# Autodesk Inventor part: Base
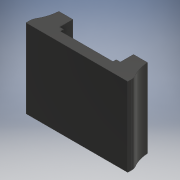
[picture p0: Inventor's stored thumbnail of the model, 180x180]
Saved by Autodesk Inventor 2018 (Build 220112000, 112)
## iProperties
Created: 2022-01
Part Number: Base
Material: Plástico, negro opaco
Document SubType Name: Modelado
Designer: Asus
Density: 0.952 g/cm^3
Appearance: Suave - Negro
Author: Asus
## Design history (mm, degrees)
sketch "Boceto1"
  geometry: L1 (135, 120)-(-135, 120); L2 (-135, 120)-(-135, -120); L3 (-135, -120)-(135, -120); L4 (135, -120)-(135, 120); L5 (135, 120)-(-135, -120); L6 (-135, 120)-(135, -120); 1 further point
  constraints: 12 end point, 2 midpoint, 2 parallel, 1 horizontal, 1 perpendicular
  dimensions: "d0" = 270 distance of L3.end L2.end; "d1" = 240 distance of L2.end L1.end
extrude "Extrusión1" new body sketch "Boceto1" distance "d2" = 80; taper "d3" = 0 deg
sketch "Boceto2"
  geometry: L1 (0, 120)-(80, 120) reference; L2 (80, 120)-(80, -120) reference; L3 (80, -120)-(0, -120) reference; L4 (0, -120)-(0, 120) reference; L5 (0, 120)-(80, 120) reference; L6 (80, 120)-(80, -120) reference; L7 (80, -120)-(0, -120) reference; L8 (0, -120)-(0, 120) reference; L9 (0, 120)-(80, 120) reference; L10 (80, 120)-(80, -120) reference; L11 (80, -120)-(0, -120) reference; L12 (0, -120)-(0, 120) reference; L13 (0, 120)-(80, 120) reference; L14 (80, 120)-(80, -120) reference; L15 (80, -120)-(0, -120) reference; L16 (0, -120)-(0, 120) reference; L17 (0, 120)-(80, 120) reference; L18 (80, 120)-(80, -120) reference; L19 (80, -120)-(0, -120) reference; L20 (0, -120)-(0, 120) reference; L21 (80, 120)-(30, 120); L22 (0, 120)-(80, 120) reference; L23 (0, -120)-(80, -120) reference; L24 (30, 120)-(80, -120); L25 (80, -120)-(80, 120); 1 further point
  constraints: 6 end point, 1 perpendicular, 1 point on line
  dimensions: "d4" = 50 distance of L1.end L21.end
extrude "Extrusión2" cut sketch "Boceto2" stored distance "d5" = 160; taper "d6" = 0 deg
sketch "Boceto3"
  geometry: L1 (-120, 0)-(-120, 80) reference; L2 (-120, 80)-(-120, 40); L3 (-120, 80)-(0, 80); L4 (120, 80)-(-120, 80) reference; L5 (0, 80)-(0, 20); L6 (0, 20)-(-20, 20); L7 (-20, 20)-(-20, 40); L8 (-20, 40)-(-120, 40); 1 further point
  constraints: 12 end point, 2 midpoint, 2 perpendicular, 1 horizontal
  dimensions: "d8" = 40 distance of L1.end L2.end; "d9" = 120 distance of L1.end L3.end (derived); "d10" = 60 distance of L3.end L5.end; "d11" = 20 distance of L5.end L6.end; "d12" = 20 distance of L6.end L7.end
extrude "Extrusión3" cut sketch "Boceto3" distance "d13" = 12.5; taper "d14" = 0 deg
sketch "Boceto4"
  geometry: L1 (0, 80)-(0, 20); L2 (0, 80)-(120, 80); L3 (120, 80)-(120, 40); L4 (0, 20)-(20, 20); L5 (20, 20)-(20, 40); L6 (20, 40)-(120, 40); 3 further points
  constraints: 12 end point, 1 horizontal, 1 perpendicular
  dimensions: "d16" = 120 distance of point (-120, 80) L1.start (derived); "d17" = 60 distance of L1.start L1.end; "d20" = 20 distance of L1.end L4.end; "d21" = 20 distance of L4.end L5.end
extrude "Extrusión4" cut sketch "Boceto4" distance "d22" = 12.5; taper "d23" = 0 deg
sketch "Boceto5"
  geometry: L1 (0, 0)-(-20, 0); L2 (-20, 0)-(-20, 20); L3 (270, 0)-(270, 80) reference; L4 (270, 80)-(270, 0); L5 (270, 0)-(290, 0); L6 (290, 0)-(290, 20); L7 (270, 0)-(0, 0) reference; L8 (0, 80)-(55, 80) reference; L9 (0, 0)-(0, 80); A1 r 122.729 centre (-122.5, 87.5) between (-20, 20) and (0, 80); A2 r 122.729 centre (392.5, 87.5) between (270, 80) and (290, 20); 1 further point
  constraints: 12 end point, 4 perpendicular, 4 point on circle, 2 centre point, 1 collinear, 1 horizontal
  dimensions: "d24" = 20 distance of L1.start L1.end; "d25" = 20 distance of L1.end L2.end; "d26" = 20 distance of L3.start L5.end; "d27" = 20 distance of L5.end L6.end; "d28" = 122.729 radius of A2
extrude "Extrusión5" join sketch "Boceto5" distance "d29" = 240; taper "d30" = 0 deg
fillet "Empalme1" dims "d31" = 30
node "Sólido1"
node "Proyectar aristas de corte1"
node "Proyectar aristas de corte2"
node "Proyectar aristas de corte3"
node "Proyectar aristas de corte4"
node "Proyectar aristas de corte5"
other parameters: "Grosor" = 0.5, "FactorK" = 4.4, "Radio_pliegue" = 0.5 (= Grosor), "Anchura_desahogo_plegado" = 0.5 (= Grosor), "Profundidad_desahogo_plegado" = 0.25 (= 0.5 x Grosor), "Tamaño_destalonado" = 2 (= 4 x Grosor), "Separación_entre_unión" = 0.01, "Remanente_mínimo" = 1 (= 2 x Grosor), "Radiodetransición" = 0.5 (= Radio_pliegue), "Tamaño_de_radio_de_Jacobi" = 0.5 (= Grosor), "TamañoSeparación" = 0.5 (= Grosor)
